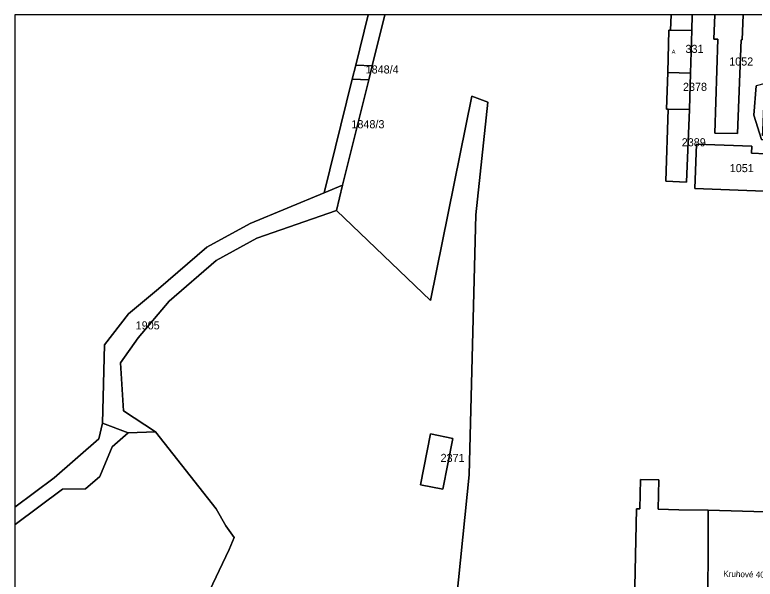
# Model space of a CAD drawing. Extents: x -564940 to -564406, y -1066466 to -1066072.
# Drawn here: x -564940.4 to -564757.1, y -1066211.8 to -1066072 of the extents above; entities that cross this region are included whole.
import ezdxf

# ---------------------------------------------------------------- set-up
doc = ezdxf.new("R2010")
doc.units = 0
for name, color, linetype in [('ft_g_stoka_ft_g_stoka_da_popis_gtc_da_6004', 7, 'Continuous'), ('ft_parcela_polygon', 7, 'Continuous'), ('ft_parcela_text', 7, 'Continuous'), ('ft_stavebni_objekt_bod', 7, 'Continuous'), ('ft_stavebni_objekt_polygon', 7, 'Continuous')]:
    doc.layers.add(name, color=color, linetype=linetype)

msp = doc.modelspace()

# ---------------------------------------------------------------- linework, layer by layer
at = {"layer": 'ft_parcela_polygon'}
for p, q in [((-564848.8, -1066072.02), (-564852.93, -1066072.02)), ((-564777.98, -1066072.02), (-564848.8, -1066072.02)), ((-564772.76, -1066072.02), (-564777.98, -1066072.02)), ((-564767.16, -1066072.02), (-564772.76, -1066072.02)), ((-564760.15, -1066072.02), (-564767.16, -1066072.02)), ((-564755.51, -1066072.02), (-564760.15, -1066072.02)), ((-564940.44, -1066193.94), (-564940.44, -1066198.28)), ((-564940.44, -1066198.28), (-564940.44, -1066233.82))]:
    msp.add_line(p, q, dxfattribs=at)
for points in [[(-564852.93, -1066072.02), (-564940.44, -1066072.02), (-564940.44, -1066193.94)], [(-564940.44, -1066193.94), (-564930.7, -1066186.69), (-564919.66, -1066177), (-564918.69, -1066173.13), (-564918.21, -1066153.76), (-564912.31, -1066146.07), (-564904.85, -1066139.86), (-564892.9, -1066129.55), (-564882.21, -1066123.71), (-564863.87, -1066116.13), (-564856.89, -1066087.99), (-564856.03, -1066084.52), (-564852.93, -1066072.02)], [(-564848.8, -1066072.02), (-564851.94, -1066084.66), (-564852.8, -1066088.13), (-564859.28, -1066114.23), (-564860.82, -1066120.45), (-564837.49, -1066142.78), (-564827.33, -1066092.18), (-564823.31, -1066093.62), (-564826.29, -1066121.56), (-564827.92, -1066185.94), (-564831.63, -1066222.49)], [(-564852.93, -1066072.02), (-564856.03, -1066084.52), (-564851.94, -1066084.66), (-564848.8, -1066072.02)], [(-564772.76, -1066072.02), (-564772.84, -1066075.93), (-564773.15, -1066086.48), (-564773.42, -1066095.48), (-564774.11, -1066113.46), (-564779.27, -1066113.22), (-564778.65, -1066095.42), (-564779.07, -1066095.41), (-564778.81, -1066086.27), (-564778.51, -1066075.78), (-564778.11, -1066075.79), (-564777.98, -1066072.02)], [(-564777.98, -1066072.02), (-564778.11, -1066075.79), (-564772.84, -1066075.93), (-564772.76, -1066072.02)], [(-564760.15, -1066072.02), (-564760.34, -1066078.24), (-564760.64, -1066078.23), (-564761.53, -1066101.45), (-564767.16, -1066101.29), (-564766.39, -1066078.08), (-564767.37, -1066078.04), (-564767.16, -1066072.02)], [(-564767.16, -1066072.02), (-564767.37, -1066078.04), (-564766.39, -1066078.08), (-564767.16, -1066101.29), (-564761.53, -1066101.45), (-564760.64, -1066078.23), (-564760.34, -1066078.24), (-564760.15, -1066072.02)], [(-564755.56, -1066102.89), (-564757.52, -1066096.87), (-564756.93, -1066089.59)], [(-564831.63, -1066222.49), (-564827.92, -1066185.94), (-564826.29, -1066121.56), (-564823.31, -1066093.62), (-564827.33, -1066092.18), (-564837.49, -1066142.78), (-564860.82, -1066120.45), (-564880.54, -1066127.36), (-564890.61, -1066132.86), (-564902.24, -1066142.89), (-564909.93, -1066152.02), (-564914.27, -1066158.19), (-564913.87, -1066164.82), (-564913.56, -1066170.05), (-564905.62, -1066175.3), (-564890.55, -1066194.35), (-564888.16, -1066198.56), (-564886.17, -1066201.49), (-564887.36, -1066204.46), (-564905.26, -1066242.1)], [(-564757.95, -1066104.55), (-564758.02, -1066106.3), (-564754.49, -1066106.44), (-564754.88, -1066115.66), (-564772.12, -1066114.99), (-564771.69, -1066104.09), (-564757.95, -1066104.55)], [(-564940.44, -1066198.28), (-564940.34, -1066198.23), (-564928.61, -1066189.5), (-564922.96, -1066189.39), (-564919.38, -1066186.35), (-564916.37, -1066178.99), (-564912.35, -1066175.55), (-564918.69, -1066173.13), (-564919.66, -1066177), (-564930.7, -1066186.69), (-564940.44, -1066193.94)], [(-564940.44, -1066233.82), (-564934.39, -1066255.21), (-564927.16, -1066265.54), (-564919.63, -1066265.35), (-564897.28, -1066253.84), (-564904.57, -1066249.93), (-564905.48, -1066245.95), (-564905.26, -1066242.1), (-564887.36, -1066204.46), (-564886.17, -1066201.49), (-564888.16, -1066198.56), (-564890.55, -1066194.35), (-564905.62, -1066175.3), (-564912.35, -1066175.55), (-564916.37, -1066178.99), (-564919.38, -1066186.35), (-564922.96, -1066189.39), (-564928.61, -1066189.5), (-564940.34, -1066198.23), (-564940.44, -1066198.28)], [(-564789.13, -1066465.63), (-564787.74, -1066462.49), (-564785.83, -1066443.87), (-564781.17, -1066395.78), (-564778.57, -1066369.76), (-564776.75, -1066348.66), (-564776.2, -1066345.68), (-564779.17, -1066345.72), (-564786.65, -1066345.83), (-564788.66, -1066294.62), (-564786.51, -1066194.35), (-564785.71, -1066194.37), (-564785.51, -1066187.08), (-564780.98, -1066187.19), (-564781.14, -1066194.46), (-564776.02, -1066194.57), (-564768.77, -1066194.68), (-564751.79, -1066195.2)], [(-564768.97, -1066215.82), (-564768.8, -1066207.93), (-564768.77, -1066194.68), (-564776.02, -1066194.57), (-564781.14, -1066194.46), (-564780.98, -1066187.19), (-564785.51, -1066187.08), (-564785.71, -1066194.37), (-564786.51, -1066194.35), (-564788.66, -1066294.62)], [(-564751.79, -1066195.2), (-564768.77, -1066194.68), (-564768.8, -1066207.93), (-564768.97, -1066215.82)]]:
    msp.add_lwpolyline(points, dxfattribs=at)
for points in [[(-564778.51, -1066075.78), (-564778.81, -1066086.27), (-564773.15, -1066086.48), (-564772.84, -1066075.93), (-564778.11, -1066075.79)], [(-564852.8, -1066088.13), (-564851.94, -1066084.66), (-564856.03, -1066084.52), (-564856.89, -1066087.99)], [(-564773.42, -1066095.48), (-564773.15, -1066086.48), (-564778.81, -1066086.27), (-564779.07, -1066095.41), (-564778.65, -1066095.42)], [(-564863.87, -1066116.13), (-564859.28, -1066114.23), (-564852.8, -1066088.13), (-564856.89, -1066087.99)], [(-564757.52, -1066096.87), (-564755.56, -1066102.89), (-564754.92, -1066102.92), (-564754.25, -1066102.96), (-564754.22, -1066101.96), (-564755.3, -1066101.92), (-564755.26, -1066100.63), (-564755.18, -1066098.48), (-564755.03, -1066094.52), (-564754.67, -1066090.29), (-564754.68, -1066089.04), (-564756.93, -1066089.59)], [(-564778.65, -1066095.42), (-564779.27, -1066113.22), (-564774.11, -1066113.46), (-564773.42, -1066095.48)], [(-564757.95, -1066104.55), (-564771.69, -1066104.09), (-564772.12, -1066114.99), (-564754.88, -1066115.66), (-564754.49, -1066106.44), (-564758.02, -1066106.3)], [(-564860.82, -1066120.45), (-564859.28, -1066114.23), (-564863.87, -1066116.13), (-564882.21, -1066123.71), (-564892.9, -1066129.55), (-564904.85, -1066139.86), (-564912.31, -1066146.07), (-564918.21, -1066153.76), (-564918.69, -1066173.13), (-564912.35, -1066175.55), (-564905.62, -1066175.3), (-564913.56, -1066170.05), (-564913.87, -1066164.82), (-564914.27, -1066158.19), (-564909.93, -1066152.02), (-564902.24, -1066142.89), (-564890.61, -1066132.86), (-564880.54, -1066127.36)], [(-564837.49, -1066175.82), (-564832, -1066176.9), (-564834.49, -1066189.52), (-564839.98, -1066188.44)], [(-564834.49, -1066189.52), (-564832, -1066176.9), (-564837.49, -1066175.82), (-564839.98, -1066188.44)]]:
    msp.add_lwpolyline(points, close=True, dxfattribs=at)
at = {"layer": 'ft_stavebni_objekt_polygon'}
for points in [[(-564778.81, -1066086.27), (-564773.15, -1066086.48), (-564772.84, -1066075.93), (-564778.11, -1066075.79), (-564778.51, -1066075.78)], [(-564772.12, -1066114.99), (-564754.88, -1066115.66), (-564754.49, -1066106.44), (-564758.02, -1066106.3), (-564757.95, -1066104.55), (-564771.69, -1066104.09)]]:
    msp.add_lwpolyline(points, close=True, dxfattribs=at)
msp.add_lwpolyline([(-564768.97, -1066215.82), (-564768.8, -1066207.93), (-564768.77, -1066194.68), (-564776.02, -1066194.57), (-564781.14, -1066194.46), (-564780.98, -1066187.19), (-564785.51, -1066187.08), (-564785.71, -1066194.37), (-564786.51, -1066194.35), (-564788.66, -1066294.62)], dxfattribs=at)

# ---------------------------------------------------------------- texts
at = {"layer": 'ft_g_stoka_ft_g_stoka_da_popis_gtc_da_6004'}
msp.add_text('Kruhové 400 TB', height=1.5, rotation=358.6709, dxfattribs=at).set_placement((-564765.05, -1066211.17))
at = {"layer": 'ft_parcela_text'}
for s, p in [('331', (-564774.4, -1066081.45)), ('1052', (-564763.58, -1066084.58)), ('1848/4', (-564853.59, -1066086.55)), ('2378', (-564775.02, -1066090.86)), ('1848/3', (-564857.11, -1066100.11)), ('2389', (-564775.33, -1066104.58)), ('1051', (-564763.44, -1066110.98)), ('1905', (-564910.52, -1066149.92)), ('2371', (-564835.03, -1066182.74))]:
    msp.add_text(s, height=2, dxfattribs=at).set_placement(p)
at = {"layer": 'ft_stavebni_objekt_bod'}
msp.add_text('A', height=1, dxfattribs=at).set_placement((-564777.81, -1066081.65))

doc.saveas('drawing.dxf')
